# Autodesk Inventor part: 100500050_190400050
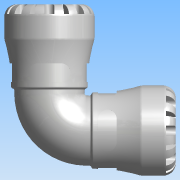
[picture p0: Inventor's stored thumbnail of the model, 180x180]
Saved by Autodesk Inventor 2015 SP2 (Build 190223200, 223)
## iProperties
Created: 2016-12
Part Number: 100500050_190400050
Material: PVC-Piping
Description: PLASSON 90° ELBOW 50X50 SERIES 1
Document SubType Name: Modeling
Designer: KIM
Mass: 664.223 g
Surface Area: 733.008 cm^2
Volume: 474.445 cm^3
Density: 1.4 g/cm^3
Appearance: Smooth - White
Author: KIM
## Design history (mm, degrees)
derived "1005.ipt"
feature "Solid1::1005.ipt"
tag "TaggingFeature1"
body "Solid1"
other parameters: "d1" = 32.76, "d3" = 62.5, "d4" = 85, "d8" = 72.25, "d13" = 9, "d14" = 9, "d15" = 0, "d17" = 360 deg, "d19" = 8 deg, "d20" = 1, "d21" = 1, "d22" = 8 deg, "d24" = 0, "d26" = 360 deg, "d33" = 8.5, "d43" = 66.3, "d51" = 0.85, "d54" = 17.5, "d55" = 11, "d57" = 17.64, "d58" = 0, "d74" = 0, "d77" = 4.16667, "d78" = 78, "d82" = 1, "d115" = 360 deg, "d207" = 90 deg, "d228" = 14.875, "d247" = 1.7, "d248" = 4.68, "d268" = 39.7375, "d269" = 4.68, "d270" = 119, "d272" = 90 deg, "d274" = 0, "d275" = 0, "E_" = 85, "l_" = 78, "A_" = 119, "d9" = 11.25, "d11" = 85, "d12" = 62.5
